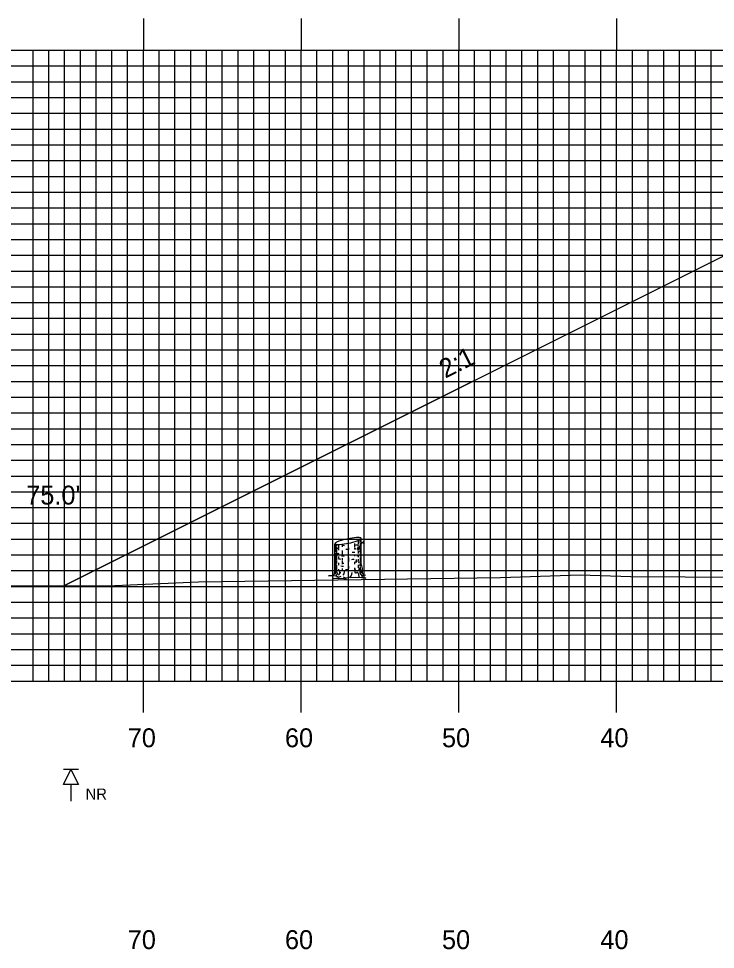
# Model space of a CAD drawing. Extents: x 1809800 to 1810143, y 442591 to 442811.
# Drawn here: x 1809887.4 to 1809931.6, y 442656.6 to 442715.7 of the extents above; entities that cross this region are included whole.
import ezdxf

# ---------------------------------------------------------------- set-up
doc = ezdxf.new("R2010")
doc.units = 0
for name, color, linetype in [('ANNOTATION', 7, 'Continuous'), ('BORING - NO REFUSAL', 7, 'Continuous'), ('D_Roadway_Centerline', 7, 'Continuous'), ('D_Roadway_SlopeLines', 7, 'Continuous'), ('D_Text_Standard', 7, 'Continuous'), ('H_V ANNOTATION', 7, 'Continuous'), ('M_Trees_Conifer_Pay', 7, 'Continuous'), ('MAJOR', 7, 'Continuous'), ('MINOR', 7, 'Continuous'), ('S_Roadway_Centerline', 7, 'Continuous')]:
    doc.layers.add(name, color=color, linetype=linetype)

msp = doc.modelspace()

# ---------------------------------------------------------------- linework, layer by layer
at = {"layer": 'BORING - NO REFUSAL'}
for p, q in [((1809891.23, 442668.065), (1809890.271, 442668.065)), ((1809890.75, 442667.106), (1809890.75, 442666.047))]:
    msp.add_line(p, q, dxfattribs=at)
msp.add_lwpolyline([(1809890.75, 442668.065), (1809891.23, 442667.106), (1809890.271, 442667.106)], close=True, dxfattribs=at)
at = {"layer": 'D_Roadway_Centerline'}
msp.add_lwpolyline([(1809890.342, 442679.722), (1809937.142, 442703.122), (1809942.35, 442705.726), (1809945.35, 442705.786), (1809953.35, 442705.946), (1809965.35, 442705.37), (1809977.35, 442704.794), (1809985.35, 442704.41), (1809988.35, 442704.266), (1809993.881, 442701.501), (1810036.244, 442680.319)], dxfattribs=at)
at = {"layer": 'D_Roadway_SlopeLines'}
msp.add_lwpolyline([(1809942.35, 442705.726), (1809890.342, 442679.722)], dxfattribs=at)
at = {"layer": 'M_Trees_Conifer_Pay'}
for p, q in [((1809908.971, 442682.575), (1809908.971, 442682.352)), ((1809909.089, 442682.636), (1809909.089, 442682.473)), ((1809909.16, 442681.061), (1809909.16, 442682.708)), ((1809907.496, 442680.651), (1809907.496, 442682.373)), ((1809907.543, 442682.335), (1809907.543, 442681.864)), ((1809907.602, 442682.324), (1809907.602, 442682.227)), ((1809907.602, 442682.152), (1809907.602, 442681.948)), ((1809907.727, 442682.316), (1809907.727, 442682.084)), ((1809907.727, 442682.043), (1809907.727, 442681.969)), ((1809907.947, 442682.337), (1809907.947, 442682.169)), ((1809908.352, 442682.105), (1809908.352, 442682.01)), ((1809908.743, 442682.379), (1809908.743, 442682.179)), ((1809908.743, 442682.122), (1809908.743, 442682.033)), ((1809908.971, 442682.263), (1809908.971, 442682.216)), ((1809909.028, 442682.08), (1809908.977, 442682.021)), ((1809909.089, 442682.406), (1809909.089, 442682.278)), ((1809909.089, 442682.091), (1809909.089, 442681.755)), ((1809907.543, 442681.8), (1809907.543, 442681.492)), ((1809907.543, 442681.444), (1809907.543, 442680.952)), ((1809907.602, 442681.891), (1809907.602, 442681.691)), ((1809907.602, 442681.644), (1809907.602, 442681.308)), ((1809907.727, 442681.566), (1809907.727, 442681.427)), ((1809907.947, 442681.932), (1809907.947, 442681.695)), ((1809907.947, 442681.45), (1809907.947, 442681.298)), ((1809908.352, 442681.492), (1809908.352, 442681.417)), ((1809908.352, 442681.393), (1809908.352, 442681.244)), ((1809908.743, 442681.685), (1809908.743, 442681.58)), ((1809908.971, 442681.881), (1809908.971, 442681.749)), ((1809908.971, 442681.638), (1809908.971, 442681.528)), ((1809908.971, 442681.393), (1809908.971, 442681.251)), ((1809909.089, 442681.718), (1809909.089, 442681.555)), ((1809909.089, 442681.508), (1809909.089, 442681.292)), ((1809907.543, 442680.898), (1809907.543, 442680.651)), ((1809907.602, 442681.255), (1809907.602, 442681.119)), ((1809907.602, 442681.02), (1809907.602, 442680.641)), ((1809907.727, 442681.156), (1809907.727, 442681.014)), ((1809907.947, 442681.255), (1809907.947, 442681.082)), ((1809907.947, 442680.804), (1809907.947, 442680.651)), ((1809908.352, 442680.952), (1809908.352, 442680.799)), ((1809908.743, 442681.213), (1809908.743, 442681.067)), ((1809908.743, 442680.835), (1809908.743, 442680.746)), ((1809908.971, 442681.024), (1809908.971, 442680.851)), ((1809909.089, 442681.261), (1809909.089, 442681.187)), ((1809909.089, 442681.146), (1809909.089, 442680.973)), ((1809907.727, 442680.752), (1809907.727, 442680.658)), ((1809907.727, 442680.258), (1809907.89, 442680.322)), ((1809908.164, 442680.194), (1809908.038, 442680.258))]:
    msp.add_line(p, q, dxfattribs=at)
for points in [[(1809908.944, 442682.169), (1809908.913, 442682.084), (1809908.909, 442682.017), (1809908.94, 442681.953)], [(1809908.977, 442682.206), (1809909.014, 442682.132), (1809909.061, 442682.189), (1809909.119, 442682.257), (1809909.211, 442682.451), (1809909.276, 442682.498), (1809909.306, 442682.505)], [(1809908.992, 442681.953), (1809909.028, 442682.08), (1809909.092, 442682.196), (1809909.123, 442682.263), (1809909.192, 442682.41)], [(1809909.206, 442682.439), (1809909.282, 442682.447), (1809909.354, 442682.348)], [(1809907.675, 442681.679), (1809907.669, 442681.774), (1809907.713, 442681.751), (1809907.713, 442681.656)], [(1809908.814, 442681.28), (1809908.827, 442681.203), (1809908.874, 442681.213), (1809908.862, 442681.38)], [(1809909.16, 442681.061), (1809909.211, 442680.799), (1809909.228, 442680.526), (1809909.285, 442680.4), (1809909.421, 442680.37), (1809909.191, 442680.332), (1809909.191, 442680.332), (1809909.197, 442680.285), (1809909.444, 442680.19), (1809909.17, 442680.207), (1809908.814, 442680.227), (1809908.493, 442680.217), (1809908.499, 442680.299), (1809908.351, 442680.217), (1809908.164, 442680.194), (1809908.188, 442680.126), (1809907.921, 442680.169), (1809907.7, 442680.143), (1809907.408, 442680.16), (1809907.696, 442680.217), (1809907.727, 442680.258), (1809907.564, 442680.316), (1809907.327, 442680.326), (1809907.087, 442680.326), (1809907.429, 442680.384), (1809907.47, 442680.464), (1809907.496, 442680.651)], [(1809908.987, 442680.773), (1809909.061, 442680.668), (1809909.066, 442680.495), (1809909.191, 442680.332)], [(1809909.086, 442680.919), (1809909.092, 442680.773), (1809909.139, 442680.705), (1809909.15, 442680.505)], [(1809907.544, 442680.604), (1809907.523, 442680.526), (1809907.503, 442680.431)], [(1809907.622, 442680.584), (1809907.628, 442680.468), (1809907.575, 442680.379), (1809907.564, 442680.316)], [(1809907.785, 442680.61), (1809907.785, 442680.479), (1809907.696, 442680.379)], [(1809908.011, 442680.37), (1809908.079, 442680.464), (1809908.106, 442680.604)], [(1809908.499, 442680.299), (1809908.574, 442680.441), (1809908.583, 442680.542)], [(1809908.75, 442680.668), (1809908.761, 442680.542), (1809908.835, 442680.499)], [(1809909.028, 442680.279), (1809909.014, 442680.417), (1809908.94, 442680.546)]]:
    msp.add_lwpolyline(points, dxfattribs=at)
for centre, radius, start, end in [((1809909.352, 442677.605), 5.179, 101.7194, 108.05939), ((1809909.352, 442677.605), 5.179, 95.37941, 101.7194), ((1809907.304, 442687.476), 5.179, 281.7194, 288.05939), ((1809908.942, 442681.963), 0.802, 79.2194, 95.37941), ((1809908.661, 442683.314), 0.802, 288.05939, 304.2194), ((1809909.045, 442682.505), 0.251, 71.05013, 79.2194), ((1809908.971, 442682.858), 0.251, 304.2194, 312.38868), ((1809909.028, 442682.677), 0.172, 300, 311.25059), ((1809909.1, 442682.664), 0.0817, 56.7194, 71.05013), ((1809909.085, 442682.734), 0.0817, 312.38868, 326.7194), ((1809909.101, 442682.594), 0.0624, 311.25059, 330), ((1809909.115, 442682.688), 0.0527, 46.92298, 56.7194), ((1809909.13, 442682.704), 0.0314, 34.2194, 46.92298), ((1809909.109, 442682.718), 0.0527, 326.7194, 336.51582), ((1809909.117, 442682.585), 0.0441, 330, 343.94846), ((1809909.134, 442682.707), 0.0264, 23.40735, 34.2194), ((1809909.138, 442682.708), 0.0226, 11.7194, 23.40735), ((1809909.129, 442682.709), 0.0314, 336.51582, 349.2194), ((1809909.127, 442682.582), 0.0334, 343.94846, 354.21506), ((1809909.138, 442682.708), 0.0226, 0.03145, 11.7194), ((1809909.134, 442682.708), 0.0264, 349.2194, 0.03145), ((1809907.528, 442682.195), 0.0334, 163.94846, 180), ((1809907.528, 442682.195), 0.0334, 180, 196.05154), ((1809907.523, 442682.373), 0.0264, 169.2194, 180.03145), ((1809907.519, 442682.373), 0.0226, 180.03145, 191.7194), ((1809907.539, 442682.198), 0.0441, 196.05154, 210), ((1809907.528, 442682.372), 0.0314, 156.51582, 169.2194), ((1809907.519, 442682.373), 0.0226, 191.7194, 203.40735), ((1809907.522, 442682.374), 0.0264, 203.40735, 214.2194), ((1809907.547, 442682.363), 0.0527, 146.7194, 156.51582), ((1809907.526, 442682.377), 0.0314, 214.2194, 226.92298), ((1809907.554, 442682.207), 0.0624, 210, 228.74941), ((1809907.571, 442682.347), 0.0817, 132.38868, 146.7194), ((1809907.541, 442682.392), 0.0527, 226.92298, 236.7194), ((1809907.557, 442682.417), 0.0817, 236.7194, 251.05013), ((1809907.627, 442682.289), 0.172, 228.74941, 240), ((1809907.685, 442682.223), 0.251, 124.2194, 132.38868), ((1809907.612, 442682.576), 0.251, 251.05013, 259.2194), ((1809907.826, 442682.634), 0.571, 240, 240.33672), ((1809907.995, 442681.767), 0.802, 108.05939, 124.2194), ((1809907.715, 442683.118), 0.802, 259.2194, 275.37941), ((1809907.826, 442682.634), 0.571, 246.85973, 257.98457), ((1809907.304, 442687.476), 5.179, 275.37941, 281.7194), ((1809908.328, 442686.385), 4.124, 264.6955, 266.73309), ((1809908.327, 442686.152), 4.124, 268.07512, 270), ((1809908.327, 442686.152), 4.124, 270, 270.35814), ((1809908.327, 442686.152), 4.124, 275.78493, 277.05584), ((1809908.328, 442686.385), 4.124, 276.23804, 278.1032), ((1809908.829, 442682.867), 0.571, 278.1032, 284.36665), ((1809908.829, 442683.022), 0.571, 284.43166, 292.41325), ((1809908.829, 442682.867), 0.571, 297.0237, 300), ((1809909.028, 442682.522), 0.172, 300, 311.25059), ((1809909.101, 442682.44), 0.0624, 311.25059, 330), ((1809909.117, 442682.43), 0.0441, 330, 343.94846), ((1809909.127, 442682.428), 0.0334, 343.94846, 354.21506), ((1809909.127, 442681.984), 0.0334, 343.94846, 354.21506), ((1809907.528, 442681.748), 0.0334, 163.94846, 180), ((1809907.528, 442681.748), 0.0334, 180, 196.05154), ((1809907.528, 442681.538), 0.0334, 163.94846, 180), ((1809907.528, 442681.538), 0.0334, 180, 196.05154), ((1809907.539, 442681.751), 0.0441, 196.05154, 210), ((1809907.539, 442681.541), 0.0441, 196.05154, 210), ((1809907.554, 442681.76), 0.0624, 210, 228.74941), ((1809907.554, 442681.55), 0.0624, 210, 228.74941), ((1809907.627, 442681.843), 0.172, 228.74941, 240), ((1809907.627, 442681.633), 0.172, 228.74941, 240), ((1809907.826, 442682.188), 0.571, 240, 240.33672), ((1809907.826, 442681.978), 0.571, 240, 246.85973), ((1809907.827, 442682.423), 0.571, 240, 247.05866), ((1809907.826, 442681.978), 0.571, 259.27072, 261.8968), ((1809908.327, 442685.495), 4.124, 261.8968, 263.14738), ((1809908.327, 442685.705), 4.124, 264.08098, 266.66759), ((1809908.327, 442685.495), 4.124, 270, 270.35814), ((1809908.327, 442685.495), 4.124, 273.14934, 275.45691), ((1809908.328, 442685.941), 4.124, 273.70524, 275.95043), ((1809908.327, 442685.705), 4.124, 277.61247, 278.1032), ((1809908.828, 442682.188), 0.571, 278.1032, 286.92962), ((1809908.829, 442682.423), 0.571, 284.44928, 297.04285), ((1809908.828, 442682.188), 0.571, 297.18959, 300), ((1809908.828, 442681.978), 0.571, 297.18959, 300), ((1809909.027, 442681.843), 0.172, 300, 311.25059), ((1809909.027, 442681.633), 0.172, 300, 311.25059), ((1809909.099, 442681.76), 0.0624, 311.25059, 330), ((1809909.099, 442681.55), 0.0624, 311.25059, 330), ((1809909.115, 442681.751), 0.0441, 330, 343.94846), ((1809909.115, 442681.541), 0.0441, 330, 343.94846), ((1809909.126, 442681.748), 0.0334, 343.94846, 354.21506), ((1809909.126, 442681.538), 0.0334, 343.94846, 354.21506), ((1809907.528, 442681.301), 0.0334, 163.94846, 180), ((1809907.528, 442681.301), 0.0334, 180, 196.05154), ((1809907.528, 442681.103), 0.0334, 163.94846, 180), ((1809907.528, 442680.908), 0.0334, 163.94846, 180), ((1809907.528, 442680.908), 0.0334, 180, 196.05154), ((1809907.539, 442681.304), 0.0441, 196.05154, 210), ((1809907.539, 442680.911), 0.0441, 196.05154, 210), ((1809907.554, 442681.313), 0.0624, 210, 228.74941), ((1809907.554, 442680.92), 0.0624, 210, 228.74941), ((1809907.627, 442681.396), 0.172, 228.74941, 240), ((1809907.627, 442681.002), 0.172, 228.74941, 240), ((1809907.826, 442681.741), 0.571, 240, 246.85973), ((1809907.815, 442681.549), 0.571, 241.23686, 248.02677), ((1809907.826, 442681.348), 0.571, 240, 246.85973), ((1809908.327, 442685.061), 4.124, 263.49906, 265.83975), ((1809908.327, 442685.258), 4.124, 264.71603, 266.31934), ((1809908.327, 442684.865), 4.124, 275.78493, 276.78961), ((1809908.828, 442681.741), 0.571, 285.39827, 297.18959), ((1809908.828, 442681.348), 0.571, 288.50673, 297.27208), ((1809908.828, 442681.543), 0.571, 289.29072, 300), ((1809909.027, 442681.198), 0.172, 300, 311.25059), ((1809909.099, 442681.115), 0.0624, 311.25059, 330), ((1809909.115, 442681.106), 0.0441, 330, 343.94846), ((1809909.126, 442681.103), 0.0334, 343.94846, 354.21506), ((1809907.528, 442680.687), 0.0334, 163.94846, 180), ((1809907.528, 442680.687), 0.0334, 180, 196.05154), ((1809907.539, 442680.69), 0.0441, 196.05154, 210), ((1809907.554, 442680.7), 0.0624, 210, 228.74941), ((1809907.627, 442680.782), 0.172, 228.74941, 240), ((1809907.826, 442681.127), 0.571, 240, 244.53138), ((1809908.327, 442684.645), 4.124, 262.44379, 263.51202), ((1809908.327, 442684.865), 4.124, 267.81166, 270), ((1809908.327, 442684.865), 4.124, 270, 270.13279), ((1809908.327, 442684.645), 4.124, 277.36842, 278.1032), ((1809908.828, 442681.127), 0.571, 278.1032, 281.63703), ((1809909.027, 442680.782), 0.172, 300, 311.25059), ((1809909.099, 442680.7), 0.0624, 311.25059, 330), ((1809909.115, 442680.69), 0.0441, 330, 343.94846), ((1809909.126, 442680.687), 0.0334, 343.94846, 354.21506)]:
    msp.add_arc(centre, radius, start, end, dxfattribs=at)
at = {"layer": 'MAJOR'}
for p, q in [((1809895.35, 442715.669), (1809895.35, 442713.665)), ((1809905.35, 442715.669), (1809905.35, 442713.665)), ((1809915.35, 442715.669), (1809915.35, 442713.665)), ((1809925.35, 442715.669), (1809925.35, 442713.665)), ((1809825.35, 442713.665), (1810105.35, 442713.665)), ((1809825.35, 442713.665), (1810105.35, 442713.665)), ((1809895.35, 442673.665), (1809895.35, 442713.665)), ((1809905.35, 442673.665), (1809905.35, 442713.665)), ((1809915.35, 442673.665), (1809915.35, 442713.665)), ((1809925.35, 442673.665), (1809925.35, 442713.665)), ((1809825.35, 442708.665), (1810105.35, 442708.665)), ((1809825.35, 442703.665), (1810105.35, 442703.665)), ((1809825.35, 442698.665), (1810105.35, 442698.665)), ((1809825.35, 442693.665), (1810105.35, 442693.665)), ((1809825.35, 442688.665), (1810105.35, 442688.665)), ((1809825.35, 442683.665), (1810105.35, 442683.665)), ((1809825.35, 442678.665), (1810105.35, 442678.665)), ((1809825.35, 442673.665), (1810105.35, 442673.665)), ((1809825.35, 442673.665), (1810105.35, 442673.665)), ((1809895.35, 442671.661), (1809895.35, 442673.665)), ((1809905.35, 442671.661), (1809905.35, 442673.665)), ((1809915.35, 442671.661), (1809915.35, 442673.665)), ((1809925.35, 442671.661), (1809925.35, 442673.665))]:
    msp.add_line(p, q, dxfattribs=at)
at = {"layer": 'MINOR'}
for p, q in [((1809888.35, 442673.665), (1809888.35, 442713.665)), ((1809889.35, 442673.665), (1809889.35, 442713.665)), ((1809890.35, 442673.665), (1809890.35, 442713.665)), ((1809891.35, 442673.665), (1809891.35, 442713.665)), ((1809892.35, 442673.665), (1809892.35, 442713.665)), ((1809893.35, 442673.665), (1809893.35, 442713.665)), ((1809894.35, 442673.665), (1809894.35, 442713.665)), ((1809896.35, 442673.665), (1809896.35, 442713.665)), ((1809897.35, 442673.665), (1809897.35, 442713.665)), ((1809898.35, 442673.665), (1809898.35, 442713.665)), ((1809899.35, 442673.665), (1809899.35, 442713.665)), ((1809900.35, 442673.665), (1809900.35, 442713.665)), ((1809901.35, 442673.665), (1809901.35, 442713.665)), ((1809902.35, 442673.665), (1809902.35, 442713.665)), ((1809903.35, 442673.665), (1809903.35, 442713.665)), ((1809904.35, 442673.665), (1809904.35, 442713.665)), ((1809906.35, 442673.665), (1809906.35, 442713.665)), ((1809907.35, 442673.665), (1809907.35, 442713.665)), ((1809908.35, 442673.665), (1809908.35, 442713.665)), ((1809909.35, 442673.665), (1809909.35, 442713.665)), ((1809910.35, 442673.665), (1809910.35, 442713.665)), ((1809911.35, 442673.665), (1809911.35, 442713.665)), ((1809912.35, 442673.665), (1809912.35, 442713.665)), ((1809913.35, 442673.665), (1809913.35, 442713.665)), ((1809914.35, 442673.665), (1809914.35, 442713.665)), ((1809916.35, 442673.665), (1809916.35, 442713.665)), ((1809917.35, 442673.665), (1809917.35, 442713.665)), ((1809918.35, 442673.665), (1809918.35, 442713.665)), ((1809919.35, 442673.665), (1809919.35, 442713.665)), ((1809920.35, 442673.665), (1809920.35, 442713.665)), ((1809921.35, 442673.665), (1809921.35, 442713.665)), ((1809922.35, 442673.665), (1809922.35, 442713.665)), ((1809923.35, 442673.665), (1809923.35, 442713.665)), ((1809924.35, 442673.665), (1809924.35, 442713.665)), ((1809926.35, 442673.665), (1809926.35, 442713.665)), ((1809927.35, 442673.665), (1809927.35, 442713.665)), ((1809928.35, 442673.665), (1809928.35, 442713.665)), ((1809929.35, 442673.665), (1809929.35, 442713.665)), ((1809930.35, 442673.665), (1809930.35, 442713.665)), ((1809931.35, 442673.665), (1809931.35, 442713.665)), ((1809825.35, 442712.665), (1810105.35, 442712.665)), ((1809825.35, 442711.665), (1810105.35, 442711.665)), ((1809825.35, 442710.665), (1810105.35, 442710.665)), ((1809825.35, 442709.665), (1810105.35, 442709.665)), ((1809825.35, 442707.665), (1810105.35, 442707.665)), ((1809825.35, 442706.665), (1810105.35, 442706.665)), ((1809825.35, 442705.665), (1810105.35, 442705.665)), ((1809825.35, 442704.665), (1810105.35, 442704.665)), ((1809825.35, 442702.665), (1810105.35, 442702.665)), ((1809825.35, 442701.665), (1810105.35, 442701.665)), ((1809825.35, 442700.665), (1810105.35, 442700.665)), ((1809825.35, 442699.665), (1810105.35, 442699.665)), ((1809825.35, 442697.665), (1810105.35, 442697.665)), ((1809825.35, 442696.665), (1810105.35, 442696.665)), ((1809825.35, 442695.665), (1810105.35, 442695.665)), ((1809825.35, 442694.665), (1810105.35, 442694.665)), ((1809825.35, 442692.665), (1810105.35, 442692.665)), ((1809825.35, 442691.665), (1810105.35, 442691.665)), ((1809825.35, 442690.665), (1810105.35, 442690.665)), ((1809825.35, 442689.665), (1810105.35, 442689.665)), ((1809825.35, 442687.665), (1810105.35, 442687.665)), ((1809825.35, 442686.665), (1810105.35, 442686.665)), ((1809825.35, 442685.665), (1810105.35, 442685.665)), ((1809825.35, 442684.665), (1810105.35, 442684.665)), ((1809825.35, 442682.665), (1810105.35, 442682.665)), ((1809825.35, 442681.665), (1810105.35, 442681.665)), ((1809825.35, 442680.665), (1810105.35, 442680.665)), ((1809825.35, 442679.665), (1810105.35, 442679.665)), ((1809825.35, 442677.665), (1810105.35, 442677.665)), ((1809825.35, 442676.665), (1810105.35, 442676.665)), ((1809825.35, 442675.665), (1810105.35, 442675.665)), ((1809825.35, 442674.665), (1810105.35, 442674.665))]:
    msp.add_line(p, q, dxfattribs=at)
at = {"layer": 'S_Roadway_Centerline'}
msp.add_lwpolyline([(1809825.35, 442679.697), (1809828.049, 442679.759), (1809855.593, 442679.798), (1809880.691, 442679.707), (1809893.543, 442679.727), (1809898.831, 442679.945), (1809917.983, 442680.221), (1809923.047, 442680.389), (1809926.253, 442680.285), (1809946.904, 442680.158), (1809966.915, 442680.356), (1809968.111, 442680.367), (1809968.217, 442680.367), (1809968.353, 442680.37), (1809981.342, 442680.669), (1809992.142, 442680.277), (1809993.934, 442680.261), (1810003.994, 442680.434)], dxfattribs=at)

# ---------------------------------------------------------------- texts
at = {"layer": 'ANNOTATION'}
msp.add_text('2:1', height=1.2, rotation=26.56505, dxfattribs=at).set_placement((1809914.491, 442692.833))
at = {"layer": 'BORING - NO REFUSAL'}
msp.add_text('NR', height=0.6998, dxfattribs=at).set_placement((1809891.683, 442666.15))
at = {"layer": 'D_Text_Standard'}
msp.add_text("75.0'", height=1.2, dxfattribs=at).set_placement((1809887.918, 442684.854))
at = {"layer": 'H_V ANNOTATION'}
for s, p in [('70', (1809894.355, 442669.465)), ('60', (1809904.323, 442669.465)), ('50', (1809914.28, 442669.465)), ('40', (1809924.323, 442669.465)), ('70', (1809894.355, 442656.665)), ('60', (1809904.323, 442656.665)), ('50', (1809914.28, 442656.665)), ('40', (1809924.323, 442656.665))]:
    msp.add_text(s, height=1.2, dxfattribs=at).set_placement(p)

doc.saveas('drawing.dxf')
